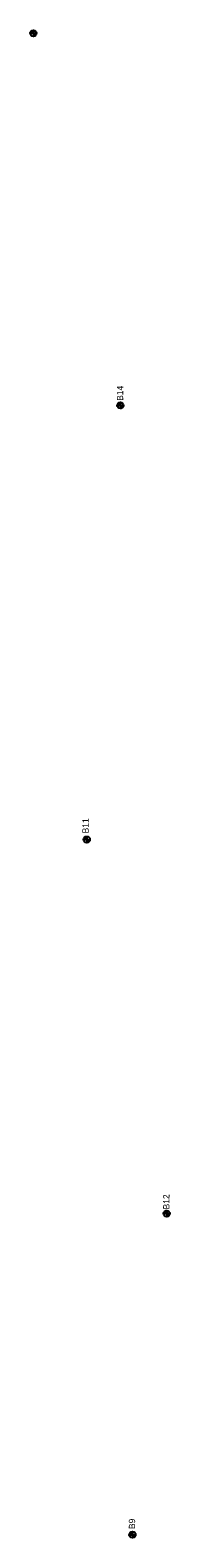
# Model space of a CAD drawing. Extents: x 327762 to 372792, y 127949 to 259367.
# Drawn here: x 361273 to 361494, y 133192 to 135571 of the extents above; entities that cross this region are included whole.
import ezdxf

# ---------------------------------------------------------------- set-up
doc = ezdxf.new("R2010")
doc.units = 0
for name, color, linetype in [('E_SOIL_BORE1 [KAPUR_CADDS_LEVELS]', 7, 'Continuous'), ('E_SOIL_BORE2 [KAPUR_CADDS_LEVELS]', 7, 'Continuous'), ('P_MARK', 7, 'Continuous')]:
    doc.layers.add(name, color=color, linetype=linetype)

msp = doc.modelspace()

# ---------------------------------------------------------------- linework, layer by layer
at = {"layer": 'P_MARK'}
for p, q in [((361273.5, 135566.2), (361283.5, 135566.2)), ((361278.5, 135571.2), (361278.5, 135561.2)), ((361415.9, 134984.1), (361415.9, 134974.1)), ((361410.9, 134979.1), (361420.9, 134979.1)), ((361357.8, 134294.1), (361367.8, 134294.1)), ((361362.8, 134299.1), (361362.8, 134289.1)), ((361484, 133703.8), (361494, 133703.8)), ((361489, 133708.8), (361489, 133698.8)), ((361435, 133202.2), (361435, 133192.2)), ((361430, 133197.2), (361440, 133197.2))]:
    msp.add_line(p, q, dxfattribs=at)
for centre in [(361278.5, 135566.2), (361415.9, 134979.1), (361362.8, 134294.1), (361489, 133703.8), (361435, 133197.2)]:
    msp.add_circle(centre, 5, dxfattribs=at)
for centre, radius, start, end in [((361278.5, 135566.2), 4.5, 89.9869, 179.9869), ((361278.5, 135566.2), 4, 89.9869, 179.9869), ((361278.5, 135566.2), 3.5, 89.9869, 179.9869), ((361278.5, 135566.2), 3, 89.9869, 179.9869), ((361278.5, 135566.2), 2.5, 89.9869, 179.9869), ((361278.5, 135566.2), 2, 89.9869, 179.9869), ((361278.5, 135566.2), 1.5, 89.9869, 179.9869), ((361278.5, 135566.2), 1, 89.9869, 179.9869), ((361278.5, 135566.2), 0.5, 89.9869, 179.9869), ((361278.5, 135566.2), 4.5, 269.9869, 359.9869), ((361278.5, 135566.2), 4, 269.9869, 359.9869), ((361278.5, 135566.2), 3.5, 269.9869, 359.9869), ((361278.5, 135566.2), 3, 269.9869, 359.9869), ((361278.5, 135566.2), 2.5, 269.9869, 359.9869), ((361278.5, 135566.2), 2, 269.9869, 359.9869), ((361278.5, 135566.2), 1.5, 269.9869, 359.9869), ((361278.5, 135566.2), 1, 269.9869, 359.9869), ((361278.5, 135566.2), 0.5, 269.9869, 359.9869), ((361415.9, 134979.1), 4.5, 89.9869, 179.9869), ((361415.9, 134979.1), 4, 89.9869, 179.9869), ((361415.9, 134979.1), 3.5, 89.9869, 179.9869), ((361415.9, 134979.1), 3, 89.9869, 179.9869), ((361415.9, 134979.1), 2.5, 89.9869, 179.9869), ((361415.9, 134979.1), 2, 89.9869, 179.9869), ((361415.9, 134979.1), 1.5, 89.9869, 179.9869), ((361415.9, 134979.1), 1, 89.9869, 179.9869), ((361415.9, 134979.1), 0.5, 89.9869, 179.9869), ((361415.9, 134979.1), 4.5, 269.9869, 359.9869), ((361415.9, 134979.1), 4, 269.9869, 359.9869), ((361415.9, 134979.1), 3.5, 269.9869, 359.9869), ((361415.9, 134979.1), 3, 269.9869, 359.9869), ((361415.9, 134979.1), 2.5, 269.9869, 359.9869), ((361415.9, 134979.1), 2, 269.9869, 359.9869), ((361415.9, 134979.1), 1.5, 269.9869, 359.9869), ((361415.9, 134979.1), 1, 269.9869, 359.9869), ((361415.9, 134979.1), 0.5, 269.9869, 359.9869), ((361362.8, 134294.1), 4.5, 89.9869, 179.9869), ((361362.8, 134294.1), 4, 89.9869, 179.9869), ((361362.8, 134294.1), 3.5, 89.9869, 179.9869), ((361362.8, 134294.1), 3, 89.9869, 179.9869), ((361362.8, 134294.1), 2.5, 89.9869, 179.9869), ((361362.8, 134294.1), 2, 89.9869, 179.9869), ((361362.8, 134294.1), 1.5, 89.9869, 179.9869), ((361362.8, 134294.1), 1, 89.9869, 179.9869), ((361362.8, 134294.1), 0.5, 89.9869, 179.9869), ((361362.8, 134294.1), 4.5, 269.9869, 359.9869), ((361362.8, 134294.1), 4, 269.9869, 359.9869), ((361362.8, 134294.1), 3.5, 269.9869, 359.9869), ((361362.8, 134294.1), 3, 269.9869, 359.9869), ((361362.8, 134294.1), 2.5, 269.9869, 359.9869), ((361362.8, 134294.1), 2, 269.9869, 359.9869), ((361362.8, 134294.1), 1.5, 269.9869, 359.9869), ((361362.8, 134294.1), 1, 269.9869, 359.9869), ((361362.8, 134294.1), 0.5, 269.9869, 359.9869), ((361489, 133703.8), 4.5, 89.9869, 179.9869), ((361489, 133703.8), 4, 89.9869, 179.9869), ((361489, 133703.8), 3.5, 89.9869, 179.9869), ((361489, 133703.8), 3, 89.9869, 179.9869), ((361489, 133703.8), 2.5, 89.9869, 179.9869), ((361489, 133703.8), 2, 89.9869, 179.9869), ((361489, 133703.8), 1.5, 89.9869, 179.9869), ((361489, 133703.8), 1, 89.9869, 179.9869), ((361489, 133703.8), 0.5, 89.9869, 179.9869), ((361489, 133703.8), 4.5, 269.9869, 359.9869), ((361489, 133703.8), 4, 269.9869, 359.9869), ((361489, 133703.8), 3.5, 269.9869, 359.9869), ((361489, 133703.8), 3, 269.9869, 359.9869), ((361489, 133703.8), 2.5, 269.9869, 359.9869), ((361489, 133703.8), 2, 269.9869, 359.9869), ((361489, 133703.8), 1.5, 269.9869, 359.9869), ((361489, 133703.8), 1, 269.9869, 359.9869), ((361489, 133703.8), 0.5, 269.9869, 359.9869), ((361435, 133197.2), 4.5, 89.9869, 179.9869), ((361435, 133197.2), 4, 89.9869, 179.9869), ((361435, 133197.2), 3.5, 89.9869, 179.9869), ((361435, 133197.2), 3, 89.9869, 179.9869), ((361435, 133197.2), 2.5, 89.9869, 179.9869), ((361435, 133197.2), 2, 89.9869, 179.9869), ((361435, 133197.2), 1.5, 89.9869, 179.9869), ((361435, 133197.2), 1, 89.9869, 179.9869), ((361435, 133197.2), 0.5, 89.9869, 179.9869), ((361435, 133197.2), 4.5, 269.9869, 359.9869), ((361435, 133197.2), 4, 269.9869, 359.9869), ((361435, 133197.2), 3.5, 269.9869, 359.9869), ((361435, 133197.2), 3, 269.9869, 359.9869), ((361435, 133197.2), 2.5, 269.9869, 359.9869), ((361435, 133197.2), 2, 269.9869, 359.9869), ((361435, 133197.2), 1.5, 269.9869, 359.9869), ((361435, 133197.2), 1, 269.9869, 359.9869), ((361435, 133197.2), 0.5, 269.9869, 359.9869)]:
    msp.add_arc(centre, radius, start, end, dxfattribs=at)

# ---------------------------------------------------------------- texts
at = {"layer": 'E_SOIL_BORE1 [KAPUR_CADDS_LEVELS]'}
msp.add_text('B14', height=10, rotation=89.9869, dxfattribs=at).set_placement((361420.3, 134986.3))
at = {"layer": 'E_SOIL_BORE2 [KAPUR_CADDS_LEVELS]'}
for s, p in [('B11', (361365.8, 134303.8)), ('B12', (361493.4, 133710.4)), ('B9', (361439.2, 133206.1))]:
    msp.add_text(s, height=10, rotation=89.9869, dxfattribs=at).set_placement(p)

doc.saveas('drawing.dxf')
